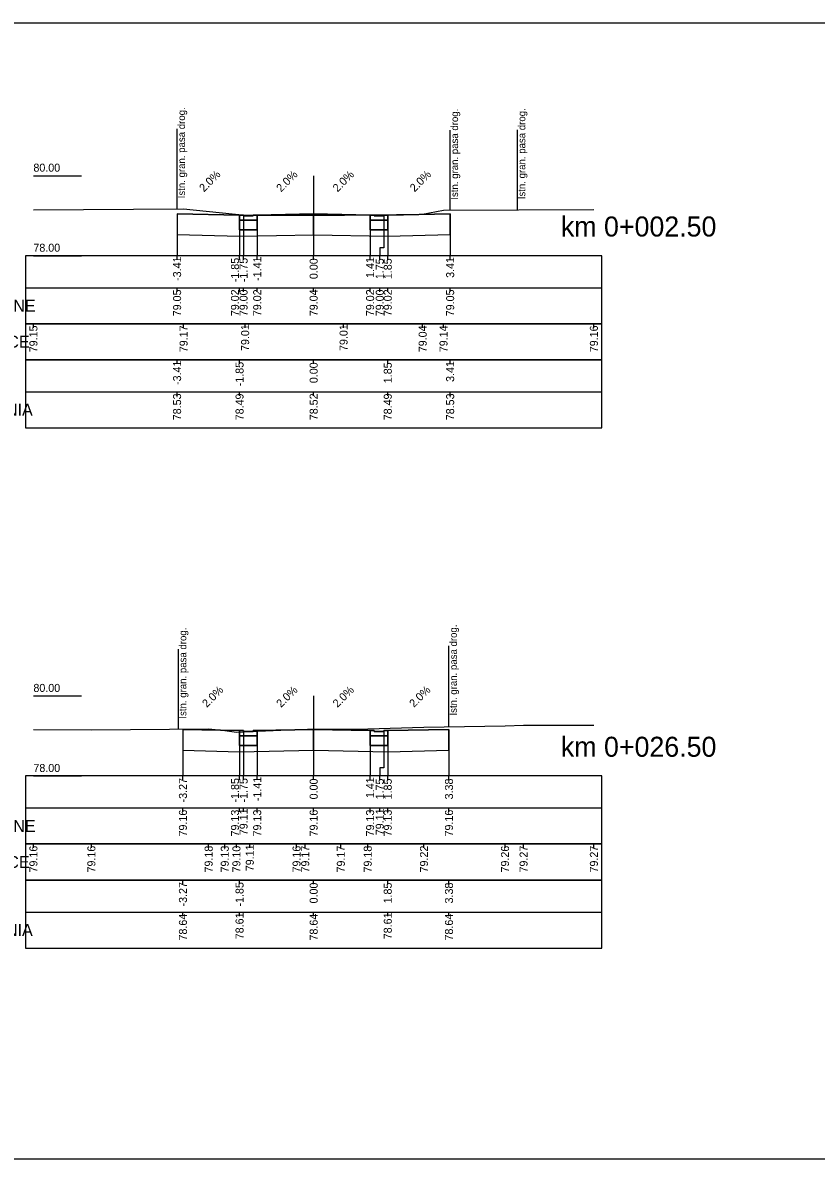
# Model space of a CAD drawing. Extents: x 7492871 to 7493499, y 5802964 to 5802992.
# Drawn here: x 7493242.92 to 7493262.74, y 5802963.88 to 5802992.28 of the extents above; entities that cross this region are included whole.
import ezdxf

# ---------------------------------------------------------------- set-up
doc = ezdxf.new("R2010")
doc.units = 0
for name, color, linetype in [('_wydruk', 7, 'Continuous'), ('opisy_ramki_pop', 7, 'Continuous'), ('pop_comp_kostka', 7, 'Continuous'), ('pop_comp_lawa', 7, 'Continuous'), ('pop_comp_scieralna', 7, 'Continuous'), ('pop_granica_istn', 7, 'Continuous'), ('pop_opis', 7, 'Continuous'), ('pop_os', 7, 'Continuous'), ('pop_pikietaz', 7, 'Continuous'), ('pop_teren', 7, 'Continuous')]:
    doc.layers.add(name, color=color, linetype=linetype)

msp = doc.modelspace()

# ---------------------------------------------------------------- linework, layer by layer
for points in [[(7493246.776, 5802987.505), (7493248.336, 5802987.474), (7493248.436, 5802987.474), (7493248.437, 5802987.454), (7493248.676, 5802987.454), (7493248.677, 5802987.474), (7493248.777, 5802987.474), (7493250.187, 5802987.502), (7493251.597, 5802987.474), (7493251.697, 5802987.474), (7493251.698, 5802987.454), (7493251.937, 5802987.454), (7493251.938, 5802987.474), (7493252.038, 5802987.474), (7493253.597, 5802987.505)], [(7493246.922, 5802974.621), (7493248.336, 5802974.593), (7493248.436, 5802974.593), (7493248.437, 5802974.573), (7493248.676, 5802974.573), (7493248.677, 5802974.593), (7493248.777, 5802974.593), (7493250.187, 5802974.621), (7493251.597, 5802974.593), (7493251.697, 5802974.593), (7493251.698, 5802974.573), (7493251.937, 5802974.573), (7493251.938, 5802974.593), (7493252.038, 5802974.593), (7493253.567, 5802974.624)]]:
    msp.add_lwpolyline(points)
at = {"layer": '_wydruk'}
msp.add_lwpolyline([(7492871.369, 5802992.281), (7493499.283, 5802992.281), (7493499.283, 5802963.881), (7492871.369, 5802963.881)], close=True, dxfattribs=at)
at = {"layer": 'opisy_ramki_pop'}
for points in [[(7493246.776, 5802986.985), (7493246.776, 5802986.659), (7493246.776, 5802986.659), (7493246.776, 5802986.459)], [(7493248.336, 5802986.945), (7493248.336, 5802986.659), (7493248.336, 5802986.659), (7493248.336, 5802986.459)], [(7493250.187, 5802986.982), (7493250.187, 5802986.659), (7493250.187, 5802986.659), (7493250.187, 5802986.459)], [(7493252.038, 5802986.945), (7493252.038, 5802986.659), (7493252.038, 5802986.659), (7493252.038, 5802986.459)], [(7493253.597, 5802986.985), (7493253.597, 5802986.659), (7493253.597, 5802986.659), (7493253.597, 5802986.459)], [(7493246.922, 5802974.101), (7493246.922, 5802973.659), (7493246.922, 5802973.659), (7493246.922, 5802973.459)], [(7493248.336, 5802974.064), (7493248.336, 5802973.659), (7493248.336, 5802973.659), (7493248.336, 5802973.459)], [(7493250.187, 5802974.101), (7493250.187, 5802973.659), (7493250.187, 5802973.659), (7493250.187, 5802973.459)], [(7493252.038, 5802974.064), (7493252.038, 5802973.659), (7493252.038, 5802973.659), (7493252.038, 5802973.459)], [(7493253.567, 5802974.104), (7493253.567, 5802973.659), (7493253.567, 5802973.659), (7493253.567, 5802973.459)]]:
    msp.add_lwpolyline(points, dxfattribs=at)
at = {"layer": 'pop_comp_kostka'}
for p, q in [((7493248.436, 5802987.474), (7493248.336, 5802987.474)), ((7493248.336, 5802987.474), (7493248.336, 5802987.344)), ((7493248.336, 5802987.344), (7493248.777, 5802987.344)), ((7493248.437, 5802987.454), (7493248.436, 5802987.474)), ((7493248.676, 5802987.454), (7493248.437, 5802987.454)), ((7493248.677, 5802987.474), (7493248.676, 5802987.454)), ((7493248.777, 5802987.474), (7493248.677, 5802987.474)), ((7493248.777, 5802987.344), (7493248.777, 5802987.474)), ((7493251.697, 5802987.474), (7493251.597, 5802987.474)), ((7493251.597, 5802987.474), (7493251.597, 5802987.344)), ((7493251.597, 5802987.344), (7493252.038, 5802987.344)), ((7493251.698, 5802987.454), (7493251.697, 5802987.474)), ((7493251.937, 5802987.454), (7493251.698, 5802987.454)), ((7493251.938, 5802987.474), (7493251.937, 5802987.454)), ((7493252.038, 5802987.474), (7493251.938, 5802987.474)), ((7493252.038, 5802987.344), (7493252.038, 5802987.474)), ((7493248.436, 5802974.593), (7493248.336, 5802974.593)), ((7493248.336, 5802974.593), (7493248.336, 5802974.463)), ((7493248.437, 5802974.573), (7493248.436, 5802974.593)), ((7493248.676, 5802974.573), (7493248.437, 5802974.573)), ((7493248.677, 5802974.593), (7493248.676, 5802974.573)), ((7493248.777, 5802974.593), (7493248.677, 5802974.593)), ((7493248.777, 5802974.463), (7493248.777, 5802974.593)), ((7493251.697, 5802974.593), (7493251.597, 5802974.593)), ((7493251.597, 5802974.593), (7493251.597, 5802974.463)), ((7493251.698, 5802974.573), (7493251.697, 5802974.593)), ((7493251.937, 5802974.573), (7493251.698, 5802974.573)), ((7493251.938, 5802974.593), (7493251.937, 5802974.573)), ((7493252.038, 5802974.593), (7493251.938, 5802974.593)), ((7493252.038, 5802974.463), (7493252.038, 5802974.593)), ((7493248.336, 5802974.463), (7493248.777, 5802974.463)), ((7493251.597, 5802974.463), (7493252.038, 5802974.463))]:
    msp.add_line(p, q, dxfattribs=at)
at = {"layer": 'pop_comp_lawa'}
for p, q in [((7493248.777, 5802987.344), (7493248.336, 5802987.344)), ((7493248.336, 5802987.344), (7493248.336, 5802987.104)), ((7493248.777, 5802987.104), (7493248.777, 5802987.344)), ((7493252.038, 5802987.344), (7493251.597, 5802987.344)), ((7493251.597, 5802987.344), (7493251.597, 5802987.104)), ((7493252.038, 5802987.104), (7493252.038, 5802987.344)), ((7493248.336, 5802987.104), (7493248.777, 5802987.104)), ((7493251.597, 5802987.104), (7493252.038, 5802987.104)), ((7493248.777, 5802974.463), (7493248.336, 5802974.463)), ((7493248.336, 5802974.463), (7493248.336, 5802974.223)), ((7493248.777, 5802974.223), (7493248.777, 5802974.463)), ((7493252.038, 5802974.463), (7493251.597, 5802974.463)), ((7493251.597, 5802974.463), (7493251.597, 5802974.223)), ((7493252.038, 5802974.223), (7493252.038, 5802974.463)), ((7493248.336, 5802974.223), (7493248.777, 5802974.223)), ((7493251.597, 5802974.223), (7493252.038, 5802974.223))]:
    msp.add_line(p, q, dxfattribs=at)
at = {"layer": 'pop_comp_scieralna'}
for p, q in [((7493248.336, 5802987.474), (7493246.776, 5802987.505)), ((7493246.776, 5802987.505), (7493246.776, 5802986.985)), ((7493248.336, 5802987.104), (7493248.336, 5802987.474)), ((7493250.187, 5802987.502), (7493248.777, 5802987.474)), ((7493248.777, 5802987.474), (7493248.777, 5802987.104)), ((7493250.187, 5802986.982), (7493250.187, 5802987.502)), ((7493251.597, 5802987.474), (7493250.187, 5802987.502)), ((7493250.187, 5802987.502), (7493250.187, 5802986.982)), ((7493251.597, 5802987.104), (7493251.597, 5802987.474)), ((7493253.597, 5802987.505), (7493252.038, 5802987.474)), ((7493252.038, 5802987.474), (7493252.038, 5802987.104)), ((7493253.597, 5802986.985), (7493253.597, 5802987.505)), ((7493248.777, 5802987.104), (7493248.336, 5802987.104)), ((7493252.038, 5802987.104), (7493251.597, 5802987.104)), ((7493246.776, 5802986.985), (7493248.336, 5802986.945)), ((7493248.336, 5802986.945), (7493250.187, 5802986.982)), ((7493250.187, 5802986.982), (7493252.038, 5802986.945)), ((7493252.038, 5802986.945), (7493253.597, 5802986.985)), ((7493248.336, 5802974.593), (7493246.922, 5802974.621)), ((7493246.922, 5802974.621), (7493246.922, 5802974.101)), ((7493248.336, 5802974.223), (7493248.336, 5802974.593)), ((7493250.187, 5802974.621), (7493248.777, 5802974.593)), ((7493248.777, 5802974.593), (7493248.777, 5802974.223)), ((7493250.187, 5802974.101), (7493250.187, 5802974.621)), ((7493251.597, 5802974.593), (7493250.187, 5802974.621)), ((7493250.187, 5802974.621), (7493250.187, 5802974.101)), ((7493251.597, 5802974.223), (7493251.597, 5802974.593)), ((7493253.567, 5802974.624), (7493252.038, 5802974.593)), ((7493252.038, 5802974.593), (7493252.038, 5802974.223)), ((7493253.567, 5802974.104), (7493253.567, 5802974.624)), ((7493246.922, 5802974.101), (7493248.336, 5802974.064)), ((7493248.777, 5802974.223), (7493248.336, 5802974.223)), ((7493248.336, 5802974.064), (7493250.187, 5802974.101)), ((7493250.187, 5802974.101), (7493252.038, 5802974.064)), ((7493252.038, 5802974.223), (7493251.597, 5802974.223)), ((7493252.038, 5802974.064), (7493253.567, 5802974.104))]:
    msp.add_line(p, q, dxfattribs=at)
at = {"layer": 'pop_granica_istn'}
for p, q in [((7493246.776, 5802988.132), (7493246.776, 5802989.632)), ((7493253.597, 5802988.098), (7493253.597, 5802989.598)), ((7493255.275, 5802988.108), (7493255.275, 5802989.608)), ((7493246.776, 5802987.632), (7493246.776, 5802988.132)), ((7493253.597, 5802987.598), (7493253.597, 5802988.098)), ((7493255.275, 5802987.608), (7493255.275, 5802988.108)), ((7493246.809, 5802975.13), (7493246.809, 5802976.63)), ((7493253.567, 5802975.207), (7493253.567, 5802976.707)), ((7493246.809, 5802974.63), (7493246.809, 5802975.13)), ((7493253.567, 5802974.707), (7493253.567, 5802975.207))]:
    msp.add_line(p, q, dxfattribs=at)
at = {"layer": 'pop_opis'}
for p, q in [((7493243.187, 5802988.459), (7493244.387, 5802988.459)), ((7493242.987, 5802986.459), (7493242.987, 5802984.759)), ((7493242.987, 5802986.459), (7493242.987, 5802984.759)), ((7493242.987, 5802986.459), (7493242.987, 5802984.759)), ((7493242.987, 5802986.459), (7493242.987, 5802984.759)), ((7493243.187, 5802986.459), (7493244.387, 5802986.459)), ((7493246.776, 5802986.359), (7493246.776, 5802986.459)), ((7493248.336, 5802986.359), (7493248.336, 5802986.459)), ((7493248.437, 5802986.359), (7493248.437, 5802986.459)), ((7493248.777, 5802986.359), (7493248.777, 5802986.459)), ((7493250.187, 5802986.359), (7493250.187, 5802986.459)), ((7493251.597, 5802986.359), (7493251.597, 5802986.459)), ((7493251.838, 5802986.359), (7493251.838, 5802986.459)), ((7493252.038, 5802986.359), (7493252.038, 5802986.459)), ((7493253.597, 5802986.359), (7493253.597, 5802986.459)), ((7493242.987, 5802985.659), (7493257.387, 5802985.659)), ((7493242.987, 5802985.659), (7493257.387, 5802985.659)), ((7493242.987, 5802985.659), (7493257.387, 5802985.659)), ((7493242.987, 5802985.659), (7493257.387, 5802985.659)), ((7493246.776, 5802985.559), (7493246.776, 5802985.659)), ((7493248.336, 5802985.559), (7493248.336, 5802985.659)), ((7493248.437, 5802985.559), (7493248.437, 5802985.659)), ((7493248.777, 5802985.559), (7493248.777, 5802985.659)), ((7493250.187, 5802985.559), (7493250.187, 5802985.659)), ((7493251.597, 5802985.559), (7493251.597, 5802985.659)), ((7493251.838, 5802985.559), (7493251.838, 5802985.659)), ((7493252.038, 5802985.559), (7493252.038, 5802985.659)), ((7493253.597, 5802985.559), (7493253.597, 5802985.659)), ((7493242.987, 5802984.759), (7493242.987, 5802983.859)), ((7493243.187, 5802984.659), (7493243.187, 5802984.759)), ((7493246.939, 5802984.659), (7493246.939, 5802984.759)), ((7493248.476, 5802984.659), (7493248.476, 5802984.759)), ((7493250.935, 5802984.659), (7493250.935, 5802984.759)), ((7493252.91, 5802984.659), (7493252.91, 5802984.759)), ((7493253.431, 5802984.659), (7493253.431, 5802984.759)), ((7493257.187, 5802984.659), (7493257.187, 5802984.759)), ((7493242.987, 5802983.859), (7493242.987, 5802982.159)), ((7493246.776, 5802983.759), (7493246.776, 5802983.859)), ((7493248.336, 5802983.759), (7493248.336, 5802983.859)), ((7493250.187, 5802983.759), (7493250.187, 5802983.859)), ((7493252.038, 5802983.759), (7493252.038, 5802983.859)), ((7493253.597, 5802983.759), (7493253.597, 5802983.859)), ((7493242.987, 5802983.059), (7493257.387, 5802983.059)), ((7493246.776, 5802982.959), (7493246.776, 5802983.059)), ((7493248.336, 5802982.959), (7493248.336, 5802983.059)), ((7493250.187, 5802982.959), (7493250.187, 5802983.059)), ((7493252.038, 5802982.959), (7493252.038, 5802983.059)), ((7493253.597, 5802982.959), (7493253.597, 5802983.059)), ((7493243.187, 5802975.459), (7493244.387, 5802975.459)), ((7493242.987, 5802973.459), (7493242.987, 5802971.759)), ((7493242.987, 5802973.459), (7493242.987, 5802971.759)), ((7493242.987, 5802973.459), (7493242.987, 5802971.759)), ((7493242.987, 5802973.459), (7493242.987, 5802971.759)), ((7493243.187, 5802973.459), (7493244.387, 5802973.459)), ((7493246.922, 5802973.359), (7493246.922, 5802973.459)), ((7493248.336, 5802973.359), (7493248.336, 5802973.459)), ((7493248.437, 5802973.359), (7493248.437, 5802973.459)), ((7493248.777, 5802973.359), (7493248.777, 5802973.459)), ((7493250.187, 5802973.359), (7493250.187, 5802973.459)), ((7493251.597, 5802973.359), (7493251.597, 5802973.459)), ((7493251.838, 5802973.359), (7493251.838, 5802973.459)), ((7493252.038, 5802973.359), (7493252.038, 5802973.459)), ((7493253.567, 5802973.359), (7493253.567, 5802973.459)), ((7493242.987, 5802972.659), (7493257.387, 5802972.659)), ((7493242.987, 5802972.659), (7493257.387, 5802972.659)), ((7493242.987, 5802972.659), (7493257.387, 5802972.659)), ((7493242.987, 5802972.659), (7493257.387, 5802972.659)), ((7493246.922, 5802972.559), (7493246.922, 5802972.659)), ((7493248.336, 5802972.559), (7493248.336, 5802972.659)), ((7493248.437, 5802972.559), (7493248.437, 5802972.659)), ((7493248.777, 5802972.559), (7493248.777, 5802972.659)), ((7493250.187, 5802972.559), (7493250.187, 5802972.659)), ((7493251.597, 5802972.559), (7493251.597, 5802972.659)), ((7493251.838, 5802972.559), (7493251.838, 5802972.659)), ((7493252.038, 5802972.559), (7493252.038, 5802972.659)), ((7493253.567, 5802972.559), (7493253.567, 5802972.659)), ((7493242.987, 5802971.759), (7493242.987, 5802970.859)), ((7493243.187, 5802971.659), (7493243.187, 5802971.759)), ((7493244.635, 5802971.659), (7493244.635, 5802971.759)), ((7493247.564, 5802971.659), (7493247.564, 5802971.759)), ((7493247.967, 5802971.659), (7493247.967, 5802971.759)), ((7493248.258, 5802971.659), (7493248.258, 5802971.759)), ((7493248.592, 5802971.659), (7493248.592, 5802971.759)), ((7493249.76, 5802971.659), (7493249.76, 5802971.759)), ((7493249.976, 5802971.659), (7493249.976, 5802971.759)), ((7493250.866, 5802971.659), (7493250.866, 5802971.759)), ((7493251.538, 5802971.659), (7493251.538, 5802971.759)), ((7493252.943, 5802971.659), (7493252.943, 5802971.759)), ((7493254.967, 5802971.659), (7493254.967, 5802971.759)), ((7493255.431, 5802971.659), (7493255.431, 5802971.759)), ((7493257.187, 5802971.659), (7493257.187, 5802971.759)), ((7493242.987, 5802970.859), (7493242.987, 5802969.159)), ((7493246.922, 5802970.759), (7493246.922, 5802970.859)), ((7493248.336, 5802970.759), (7493248.336, 5802970.859)), ((7493250.187, 5802970.759), (7493250.187, 5802970.859)), ((7493252.038, 5802970.759), (7493252.038, 5802970.859)), ((7493253.567, 5802970.759), (7493253.567, 5802970.859)), ((7493242.987, 5802970.059), (7493257.387, 5802970.059)), ((7493246.922, 5802969.959), (7493246.922, 5802970.059)), ((7493248.336, 5802969.959), (7493248.336, 5802970.059)), ((7493250.187, 5802969.959), (7493250.187, 5802970.059)), ((7493252.038, 5802969.959), (7493252.038, 5802970.059)), ((7493253.567, 5802969.959), (7493253.567, 5802970.059))]:
    msp.add_line(p, q, dxfattribs=at)
for points in [[(7493246.776, 5802987.505), (7493246.776, 5802986.659), (7493246.776, 5802986.659), (7493246.776, 5802986.459)], [(7493248.336, 5802987.474), (7493248.336, 5802986.659), (7493248.336, 5802986.659), (7493248.336, 5802986.459)], [(7493248.437, 5802987.454), (7493248.437, 5802986.659), (7493248.437, 5802986.659), (7493248.437, 5802986.459)], [(7493248.777, 5802987.474), (7493248.777, 5802986.659), (7493248.777, 5802986.659), (7493248.777, 5802986.459)], [(7493250.187, 5802987.502), (7493250.187, 5802986.659), (7493250.187, 5802986.659), (7493250.187, 5802986.459)], [(7493251.597, 5802987.474), (7493251.597, 5802986.659), (7493251.597, 5802986.659), (7493251.597, 5802986.459)], [(7493251.937, 5802987.454), (7493251.937, 5802986.659), (7493251.838, 5802986.659), (7493251.838, 5802986.459)], [(7493252.038, 5802987.474), (7493252.038, 5802986.659), (7493252.038, 5802986.659), (7493252.038, 5802986.459)], [(7493253.597, 5802987.505), (7493253.597, 5802986.659), (7493253.597, 5802986.659), (7493253.597, 5802986.459)], [(7493246.922, 5802974.621), (7493246.922, 5802973.659), (7493246.922, 5802973.659), (7493246.922, 5802973.459)], [(7493248.336, 5802974.593), (7493248.336, 5802973.659), (7493248.336, 5802973.659), (7493248.336, 5802973.459)], [(7493248.437, 5802974.573), (7493248.437, 5802973.659), (7493248.437, 5802973.659), (7493248.437, 5802973.459)], [(7493248.777, 5802974.593), (7493248.777, 5802973.659), (7493248.777, 5802973.659), (7493248.777, 5802973.459)], [(7493250.187, 5802974.621), (7493250.187, 5802973.659), (7493250.187, 5802973.659), (7493250.187, 5802973.459)], [(7493251.597, 5802974.593), (7493251.597, 5802973.659), (7493251.597, 5802973.659), (7493251.597, 5802973.459)], [(7493251.937, 5802974.573), (7493251.937, 5802973.659), (7493251.838, 5802973.659), (7493251.838, 5802973.459)], [(7493252.038, 5802974.593), (7493252.038, 5802973.659), (7493252.038, 5802973.659), (7493252.038, 5802973.459)], [(7493253.567, 5802974.624), (7493253.567, 5802973.659), (7493253.567, 5802973.659), (7493253.567, 5802973.459)]]:
    msp.add_lwpolyline(points, dxfattribs=at)
for points in [[(7493242.987, 5802986.459), (7493242.987, 5802984.759), (7493257.387, 5802984.759), (7493257.387, 5802986.459)], [(7493242.987, 5802986.459), (7493242.987, 5802984.759), (7493257.387, 5802984.759), (7493257.387, 5802986.459)], [(7493242.987, 5802986.459), (7493242.987, 5802984.759), (7493257.387, 5802984.759), (7493257.387, 5802986.459)], [(7493242.987, 5802986.459), (7493242.987, 5802984.759), (7493257.387, 5802984.759), (7493257.387, 5802986.459)], [(7493242.987, 5802984.759), (7493242.987, 5802983.859), (7493257.387, 5802983.859), (7493257.387, 5802984.759)], [(7493242.987, 5802983.859), (7493242.987, 5802982.159), (7493257.387, 5802982.159), (7493257.387, 5802983.859)], [(7493242.987, 5802973.459), (7493242.987, 5802971.759), (7493257.387, 5802971.759), (7493257.387, 5802973.459)], [(7493242.987, 5802973.459), (7493242.987, 5802971.759), (7493257.387, 5802971.759), (7493257.387, 5802973.459)], [(7493242.987, 5802973.459), (7493242.987, 5802971.759), (7493257.387, 5802971.759), (7493257.387, 5802973.459)], [(7493242.987, 5802973.459), (7493242.987, 5802971.759), (7493257.387, 5802971.759), (7493257.387, 5802973.459)], [(7493242.987, 5802971.759), (7493242.987, 5802970.859), (7493257.387, 5802970.859), (7493257.387, 5802971.759)], [(7493242.987, 5802970.859), (7493242.987, 5802969.159), (7493257.387, 5802969.159), (7493257.387, 5802970.859)]]:
    msp.add_lwpolyline(points, close=True, dxfattribs=at)
at = {"layer": 'pop_os'}
for p, q in [((7493250.187, 5802988.459), (7493250.187, 5802986.459)), ((7493250.187, 5802975.459), (7493250.187, 5802973.459))]:
    msp.add_line(p, q, dxfattribs=at)
at = {"layer": 'pop_teren'}
for points in [[(7493243.187, 5802987.608), (7493246.939, 5802987.633), (7493248.476, 5802987.468), (7493248.478, 5802987.468), (7493248.485, 5802987.468), (7493248.497, 5802987.468), (7493250.935, 5802987.468), (7493250.957, 5802987.468), (7493252.91, 5802987.5), (7493253.431, 5802987.597), (7493257.187, 5802987.617)], [(7493243.187, 5802974.616), (7493244.635, 5802974.615), (7493247.564, 5802974.635), (7493247.967, 5802974.592), (7493248.258, 5802974.556), (7493248.592, 5802974.57), (7493249.76, 5802974.623), (7493249.976, 5802974.624), (7493250.033, 5802974.625), (7493250.866, 5802974.628), (7493251.538, 5802974.635), (7493252.943, 5802974.681), (7493254.967, 5802974.715), (7493255.431, 5802974.727), (7493257.187, 5802974.726)]]:
    msp.add_lwpolyline(points, dxfattribs=at)

# ---------------------------------------------------------------- texts
at = {"layer": 'pop_granica_istn'}
for p in [(7493246.975, 5802987.893), (7493253.795, 5802987.859), (7493255.474, 5802987.869), (7493247.007, 5802974.891), (7493253.765, 5802974.968)]:
    msp.add_text('Istn. gran. pasa drog.', height=0.18, rotation=90, dxfattribs=at).set_placement(p)
at = {"layer": 'pop_opis'}
for s, height, p in [('80.00', 0.2, (7493243.187, 5802988.559)), ('78.00', 0.2, (7493243.187, 5802986.559)), ('RZĘDNE PROJEKTOWANE', 0.3, (7493238.115, 5802985.059)), ('RZĘDNE PROJEKTOWANE', 0.3, (7493238.115, 5802985.059)), ('RZĘDNE PROJEKTOWANE', 0.3, (7493238.115, 5802985.059)), ('RZĘDNE PROJEKTOWANE', 0.3, (7493238.115, 5802985.059)), ('RZĘDNE ISTNIEJĄCE', 0.3, (7493239.012, 5802984.159)), ('RZĘDNE KORYTOWANIA', 0.3, (7493238.401, 5802982.459)), ('80.00', 0.2, (7493243.187, 5802975.559)), ('78.00', 0.2, (7493243.187, 5802973.559)), ('RZĘDNE PROJEKTOWANE', 0.3, (7493238.115, 5802972.059)), ('RZĘDNE PROJEKTOWANE', 0.3, (7493238.115, 5802972.059)), ('RZĘDNE PROJEKTOWANE', 0.3, (7493238.115, 5802972.059)), ('RZĘDNE PROJEKTOWANE', 0.3, (7493238.115, 5802972.059)), ('RZĘDNE ISTNIEJĄCE', 0.3, (7493239.012, 5802971.159)), ('RZĘDNE KORYTOWANIA', 0.3, (7493238.401, 5802969.459))]:
    msp.add_text(s, height=height, dxfattribs=at).set_placement(p)
for s, rotation, p in [('2.0%', 45, (7493247.447, 5802988.04)), ('2.0%', 45, (7493249.373, 5802988.038)), ('2.0%', 45, (7493250.783, 5802988.038)), ('2.0%', 45, (7493252.709, 5802988.04)), ('-3.41', 90, (7493246.876, 5802985.829)), ('-1.85', 90, (7493248.322, 5802985.796)), ('-1.75', 90, (7493248.537, 5802985.796)), ('-1.41', 90, (7493248.877, 5802985.829)), ('0.00', 90, (7493250.287, 5802985.874)), ('1.41', 90, (7493251.697, 5802985.905)), ('1.75', 90, (7493251.938, 5802985.873)), ('1.85', 90, (7493252.138, 5802985.873)), ('3.41', 90, (7493253.697, 5802985.905)), ('79.05', 90, (7493246.876, 5802984.945)), ('79.02', 90, (7493248.322, 5802984.948)), ('79.00', 90, (7493248.537, 5802984.947)), ('79.02', 90, (7493248.877, 5802984.948)), ('79.04', 90, (7493250.287, 5802984.947)), ('79.02', 90, (7493251.697, 5802984.948)), ('79.00', 90, (7493251.938, 5802984.947)), ('79.02', 90, (7493252.138, 5802984.948)), ('79.05', 90, (7493253.697, 5802984.945)), ('79.15', 90, (7493243.287, 5802984.045)), ('79.17', 90, (7493247.039, 5802984.047)), ('79.01', 90, (7493248.576, 5802984.078)), ('79.01', 90, (7493251.035, 5802984.078)), ('79.04', 90, (7493253.01, 5802984.047)), ('79.14', 90, (7493253.531, 5802984.047)), ('79.16', 90, (7493257.287, 5802984.047)), ('-3.41', 90, (7493246.876, 5802983.229)), ('-1.85', 90, (7493248.436, 5802983.196)), ('0.00', 90, (7493250.287, 5802983.274)), ('1.85', 90, (7493252.138, 5802983.273)), ('3.41', 90, (7493253.697, 5802983.305)), ('78.53', 90, (7493246.876, 5802982.347)), ('78.49', 90, (7493248.436, 5802982.346)), ('78.52', 90, (7493250.287, 5802982.348)), ('78.49', 90, (7493252.138, 5802982.346)), ('78.53', 90, (7493253.697, 5802982.347)), ('2.0%', 45, (7493247.52, 5802975.157)), ('2.0%', 45, (7493249.373, 5802975.157)), ('2.0%', 45, (7493250.783, 5802975.157)), ('2.0%', 45, (7493252.694, 5802975.158)), ('-1.41', 90, (7493248.877, 5802972.829)), ('-3.27', 90, (7493247.022, 5802972.798)), ('-1.85', 90, (7493248.322, 5802972.796)), ('-1.75', 90, (7493248.537, 5802972.796)), ('0.00', 90, (7493250.287, 5802972.874)), ('1.41', 90, (7493251.697, 5802972.905)), ('1.75', 90, (7493251.938, 5802972.873)), ('1.85', 90, (7493252.138, 5802972.873)), ('3.38', 90, (7493253.667, 5802972.873)), ('79.16', 90, (7493247.022, 5802971.947)), ('79.13', 90, (7493248.322, 5802971.947)), ('79.11', 90, (7493248.537, 5802971.978)), ('79.13', 90, (7493248.877, 5802971.947)), ('79.16', 90, (7493250.287, 5802971.947)), ('79.13', 90, (7493251.697, 5802971.947)), ('79.11', 90, (7493251.938, 5802971.978)), ('79.13', 90, (7493252.138, 5802971.947)), ('79.16', 90, (7493253.667, 5802971.947)), ('79.11', 90, (7493248.692, 5802971.078)), ('79.16', 90, (7493243.287, 5802971.047)), ('79.16', 90, (7493244.735, 5802971.047)), ('79.18', 90, (7493247.664, 5802971.046)), ('79.13', 90, (7493248.067, 5802971.047)), ('79.10', 90, (7493248.358, 5802971.047)), ('79.16', 90, (7493249.86, 5802971.047)), ('79.17', 90, (7493250.076, 5802971.047)), ('79.17', 90, (7493250.966, 5802971.047)), ('79.18', 90, (7493251.638, 5802971.046)), ('79.22', 90, (7493253.043, 5802971.048)), ('79.26', 90, (7493255.067, 5802971.047)), ('79.27', 90, (7493255.531, 5802971.047)), ('79.27', 90, (7493257.287, 5802971.047)), ('-3.27', 90, (7493247.022, 5802970.198)), ('-1.85', 90, (7493248.436, 5802970.196)), ('0.00', 90, (7493250.287, 5802970.274)), ('1.85', 90, (7493252.138, 5802970.273)), ('3.38', 90, (7493253.667, 5802970.273)), ('78.61', 90, (7493248.436, 5802969.378)), ('78.61', 90, (7493252.138, 5802969.378)), ('78.64', 90, (7493247.022, 5802969.347)), ('78.64', 90, (7493250.287, 5802969.347)), ('78.64', 90, (7493253.667, 5802969.347))]:
    msp.add_text(s, height=0.2, rotation=rotation, dxfattribs=at).set_placement(p)
at = {"layer": 'pop_pikietaz'}
for s, p in [('km 0+002.50', (7493256.363, 5802986.939)), ('km 0+026.50', (7493256.363, 5802973.939))]:
    msp.add_text(s, height=0.5, dxfattribs=at).set_placement(p)

doc.saveas('drawing.dxf')
